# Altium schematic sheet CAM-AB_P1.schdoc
size 420 x 297 mm; Symbol: Drawing-Symbol_A4; @Project Name: FPGA_motors_V3_0_4; @Page Count: 1; @Update Date: 2025-12-23; @Create Date: 2025-12-23; @Schematic Name: CAM-AB; @Page No: 1; @Page Name: P1; Company: EasyEDA.com; Version: V1.0; Page Size: A4; @Create Time: 13:22:03; @Update Time: 14:22:09; Border: 1; Width: 1655; Height: 1170; Region Start: 1; X Region Count: 6; Y Region Count: 4; Blade Width: 10; Title Block Position: 3; Device: Drawing-Symbol_A4
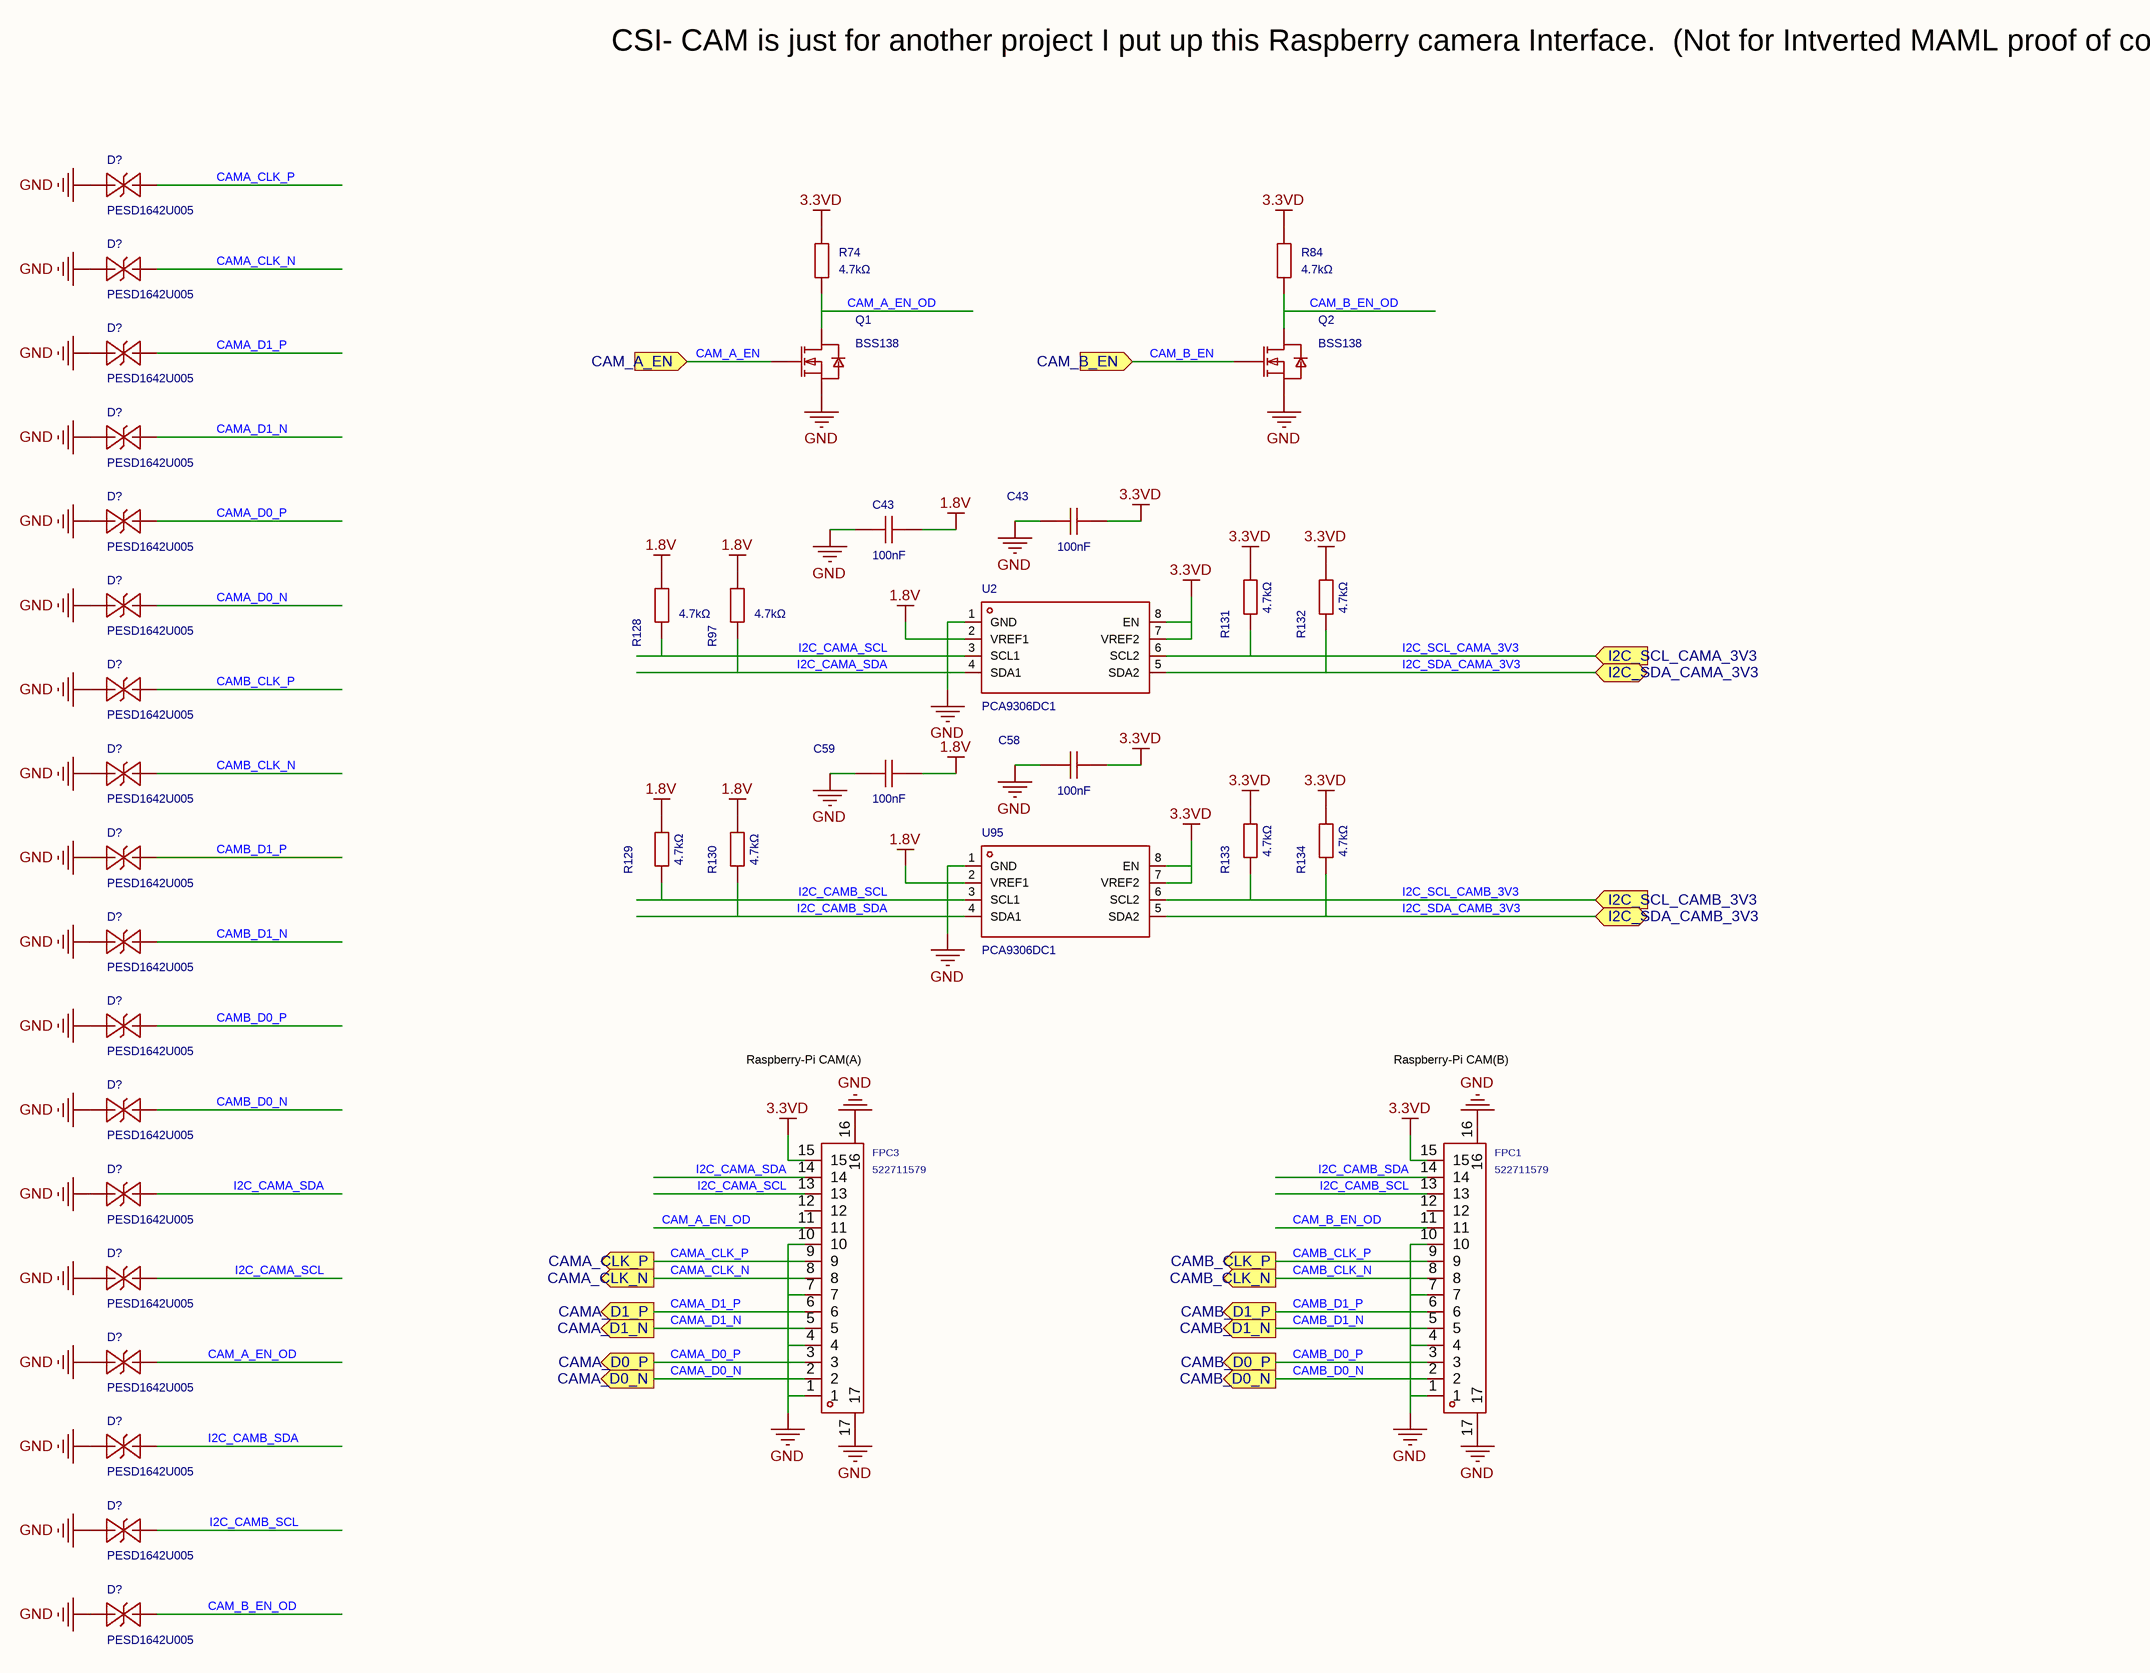
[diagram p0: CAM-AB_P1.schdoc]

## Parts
(Parts that share a designator on the sheet are numbered #1, #2 ... from top to bottom, then left to right.)
C43#1  100nF  [C0402]
C43#2  100nF  [C0402]
C58  100nF  [C0402]
C59  100nF  [C0402]
D?#1  PESD1642U005  [D0402-BI]
D?#2  PESD1642U005  [D0402-BI]
D?#3  PESD1642U005  [D0402-BI]
D?#4  PESD1642U005  [D0402-BI]
D?#5  PESD1642U005  [D0402-BI]
D?#6  PESD1642U005  [D0402-BI]
D?#7  PESD1642U005  [D0402-BI]
D?#8  PESD1642U005  [D0402-BI]
D?#9  PESD1642U005  [D0402-BI]
D?#10  PESD1642U005  [D0402-BI]
D?#11  PESD1642U005  [D0402-BI]
D?#12  PESD1642U005  [D0402-BI]
D?#13  PESD1642U005  [D0402-BI]
D?#14  PESD1642U005  [D0402-BI]
D?#15  PESD1642U005  [D0402-BI]
D?#16  PESD1642U005  [D0402-BI]
D?#17  PESD1642U005  [D0402-BI]
D?#18  PESD1642U005  [D0402-BI]
FPC1  522711579  [FPC-SMD_522711579]
FPC3  522711579  [FPC-SMD_522711579]
Q1  BSS138  [SOT-23-3_L2.9-W1.3-P1.90-LS2.4-BR-1]
Q2  BSS138  [SOT-23-3_L2.9-W1.3-P1.90-LS2.4-BR-1]
R74  4.7kΩ  [R0402]
R84  4.7kΩ  [R0402]
R97  4.7kΩ  [R0402]
R128  4.7kΩ  [R0402]
R129  4.7kΩ  [R0402]
R130  4.7kΩ  [R0402]
R131  4.7kΩ  [R0402]
R132  4.7kΩ  [R0402]
R133  4.7kΩ  [R0402]
R134  4.7kΩ  [R0402]
U2  PCA9306DC1  [VSSOP-8_L2.4-W2.1-P0.50-LS3.2-BR]
U95  PCA9306DC1  [VSSOP-8_L2.4-W2.1-P0.50-LS3.2-BR]

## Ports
CAM_A_EN (in), CAM_B_EN (in), CAMA_CLK_N (out), CAMA_CLK_P (out), CAMA_D0_N (out), CAMA_D0_P (out), CAMA_D1_N (out), CAMA_D1_P (out), CAMB_CLK_N (out), CAMB_CLK_P (out), CAMB_D0_N (out), CAMB_D0_P (out), CAMB_D1_N (out), CAMB_D1_P (out), I2C_SCL_CAMA_3V3 (in), I2C_SCL_CAMB_3V3 (in), I2C_SDA_CAMA_3V3 (bidir), I2C_SDA_CAMB_3V3 (bidir)

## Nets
1.8V: C43#2.2 C59.2 R97.2 R128.2 R129.2 R130.2 U2.2(VREF1) U95.2(VREF1)
3.3VD: C43#1.2 C58.2 FPC1.15 FPC3.15 R74.1 R84.1 R131.2 R132.2 R133.2 R134.2 U2.7(VREF2) U2.8(EN) U95.7(VREF2) U95.8(EN)
GND: C43#1.1 C43#2.1 C58.1 C59.1 D?#1.1 D?#2.1 D?#3.1 D?#4.1 D?#5.1 D?#6.1 D?#7.1 D?#8.1 D?#9.1 D?#10.1 D?#11.1 D?#12.1 D?#13.1 D?#14.1 D?#15.1 D?#16.1 D?#17.1 D?#18.1 FPC1.1 FPC1.4 FPC1.7 FPC1.10 FPC1.16 FPC1.17 FPC3.1 FPC3.4 FPC3.7 FPC3.10 FPC3.16 FPC3.17 Q1.2(S) Q2.2(S) U2.1(GND) U95.1(GND)
CAM_A_EN: Q1.1(G) ; port CAM_A_EN
CAM_A_EN_OD: D?#15.2 FPC3.11 Q1.3(D) R74.2
CAM_B_EN: Q2.1(G) ; port CAM_B_EN
CAM_B_EN_OD: D?#18.2 FPC1.11 Q2.3(D) R84.2
CAMA_CLK_N: D?#2.2 FPC3.8 ; port CAMA_CLK_N
CAMA_CLK_P: D?#1.2 FPC3.9 ; port CAMA_CLK_P
CAMA_D0_N: D?#6.2 FPC3.2 ; port CAMA_D0_N
CAMA_D0_P: D?#5.2 FPC3.3 ; port CAMA_D0_P
CAMA_D1_N: D?#4.2 FPC3.5 ; port CAMA_D1_N
CAMA_D1_P: D?#3.2 FPC3.6 ; port CAMA_D1_P
CAMB_CLK_N: D?#8.2 FPC1.8 ; port CAMB_CLK_N
CAMB_CLK_P: D?#7.2 FPC1.9 ; port CAMB_CLK_P
CAMB_D0_N: D?#12.2 FPC1.2 ; port CAMB_D0_N
CAMB_D0_P: D?#11.2 FPC1.3 ; port CAMB_D0_P
CAMB_D1_N: D?#10.2 FPC1.5 ; port CAMB_D1_N
CAMB_D1_P: D?#9.2 FPC1.6 ; port CAMB_D1_P
I2C_CAMA_SCL: D?#14.2 FPC3.13 R128.1 U2.3(SCL1)
I2C_CAMA_SDA: D?#13.2 FPC3.14 R97.1 U2.4(SDA1)
I2C_CAMB_SCL: D?#17.2 FPC1.13 R129.1 U95.3(SCL1)
I2C_CAMB_SDA: D?#16.2 FPC1.14 R130.1 U95.4(SDA1)
I2C_SCL_CAMA_3V3: R131.1 U2.6(SCL2) ; port I2C_SCL_CAMA_3V3
I2C_SCL_CAMB_3V3: R133.1 U95.6(SCL2) ; port I2C_SCL_CAMB_3V3
I2C_SDA_CAMA_3V3: R132.1 U2.5(SDA2) ; port I2C_SDA_CAMA_3V3
I2C_SDA_CAMB_3V3: R134.1 U95.5(SDA2) ; port I2C_SDA_CAMB_3V3

Not connected (* = marked no-connect by the designer): FPC1 12; FPC3 12

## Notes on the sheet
- CSI- CAM is just for another project I put up this Raspberry camera Interface.  (Not for Intverted MAML proof of concept)
- Raspberry-Pi CAM(A)
- Raspberry-Pi CAM(B)

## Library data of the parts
C43#1 C43#2 C58 C59 = CL05B104KB54PNC: Capacitance: Tolerance:±10% Tolerance:±10% Voltage Rated: Temperature Coefficient:; Manufacturer: SAMSUNG(三星); Check: true; AddInBom: yes; ModelId: b7d13df3e9464d7a99d0651d1a5b4d57; ModelName: C0402_L1.0-W0.5-H0.5; ModelTransform: 39.37,19.685,0,0,0,0,0,0,0; Tolerance: ±10%
D?#1-D?#18 = PESD1642U005: Polarity:Bidirectional Clamping Voltage:35V Reverse Leakage Current (Ir):100nA Number of Channels:1 Operating Temperature:-55℃~+125℃ Operating Temperature:-55℃~+125℃ level of protection:IEC 61000-4-2 Type:ESD Junction Capacitance:0.05pF; Manufacturer: Leiditech(雷卯电子); Add into BOM: yes; ModelId: 9d627b6ad13249ab8e6fe12f8c614d23; ModelName: D0402_L1.0-W0.5-H0.5; ModelTransform: 39.37,19.685,0,0,0,0,0,0,0; Clamping Voltage: 35V; Reverse Leakage Current (Ir): 100nA; Number of Channels: 1; Type: ESD; Junction Capacitance: 0.05pF
FPC1 FPC3 = 522711579: Locking Feature:Hinged Lid Contact Type:Bottom Contact Number of Contacts:15P Pitch:1mm Mounting Type:Surface Mount, Right Angle Contact Material:Phosphor bronze Contact Plating:Sn-Bi Operating Temperature:-40℃~+85℃ Operating Temperature:-40℃~+85℃ Rated V; Manufacturer: MOLEX; AddInBom: yes; Number of Contacts: 15P; Pitch: 1mm; Rated Voltage (Max): 50V; Current Rating (Max): 500mA; ModelId: 03f8c5614af14deea9c7875ecb43a1980819f05c4eef4c71ace90d822a990e87; ModelTransform: 866.14,342.519,0,0,0,0,0,-97.834,0
Q1 Q2 = BSS138: Type:1 N-channel Drain Source Voltage (Vdss): Continuous Drain Current (Id): Drain Source On Resistance (RDS(on)@Vgs,Id):3.5Ω@4.5V,220mA Power Dissipation (Pd): Gate Threshold Voltage (Vgs(th)@Id):1.6V@1mA Total Gate Charge (Qg@Vgs):- Input Capacitance (C; Manufacturer: KUU; Symbol: BSS138_C3015220; AddInBom: yes; ModelId: 62a57c6760504a01965db6419a6d07df; ModelName: SOT-23-3P_L2.9-W1.3-H1.0-LS2.4-P0.95; ModelTransform: 98.425,114.173,0,180,0,0,0.0005,-0.0005,0; Input Capacitance (Ciss@Vds): 50pF@25V
R74 R84 R97 R128-R130 = 0402WGF4701TCE: Type:Thick Film Resistors Resistance:4.7kΩ Tolerance:±1% Tolerance:±1% Power(Watts): Overload Voltage (Max): Temperature Coefficient:±100ppm/℃ Temperature Coefficient:±100ppm/℃ Operating Temperature Range:-55℃~+155℃ Operating Temperature Range:-55℃~+155℃; Manufacturer: UNI-ROYAL(厚声); Symbol: RT0402BRD074K7L; AddInBom: yes; ModelId: efdecb7dae4442949d28eecaf748420f0819f05c4eef4c71ace90d822a990e87; ModelName: R0402_L1.0-W0.5-H0.4; ModelTransform: 39.37,19.685,0,0,0,0,0,0,0; Tolerance: ±1%; Power(Watts): 62.5mW; Voltage-Supply(Max): 50V
R131-R134 = 0402WGF4701TCE: Type:Thick Film Resistors Resistance:4.7kΩ Tolerance:±1% Tolerance:±1% Power(Watts): Overload Voltage (Max): Temperature Coefficient:±100ppm/℃ Temperature Coefficient:±100ppm/℃ Operating Temperature Range:-55℃~+155℃ Operating Temperature Range:-55℃~+155℃; Manufacturer: UNI-ROYAL(厚声); Add into BOM: no; Symbol: RT0402BRD074K7L; ConvertToPcb: yes; ModelId: efdecb7dae4442949d28eecaf748420f0819f05c4eef4c71ace90d822a990e87; ModelName: R0402_L1.0-W0.5-H0.4; ModelTransform: 39.37,19.685,0,0,0,0,0,0,0; Tolerance: ±1%; Power(Watts): 62.5mW; Voltage-Supply(Max): 50V
U2 U95 = PCA9306DC1: Manufacturer: NXP(恩智浦); AddInBom: yes; ModelId: eea7862749434464be9d0e2ff9cbca30; ModelName: VSSOP-8_L2.0-W2.3-H0.9-LS3.1-P0.50; ModelTransform: 138.289,78.74,0,180,0,0,0,0,0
